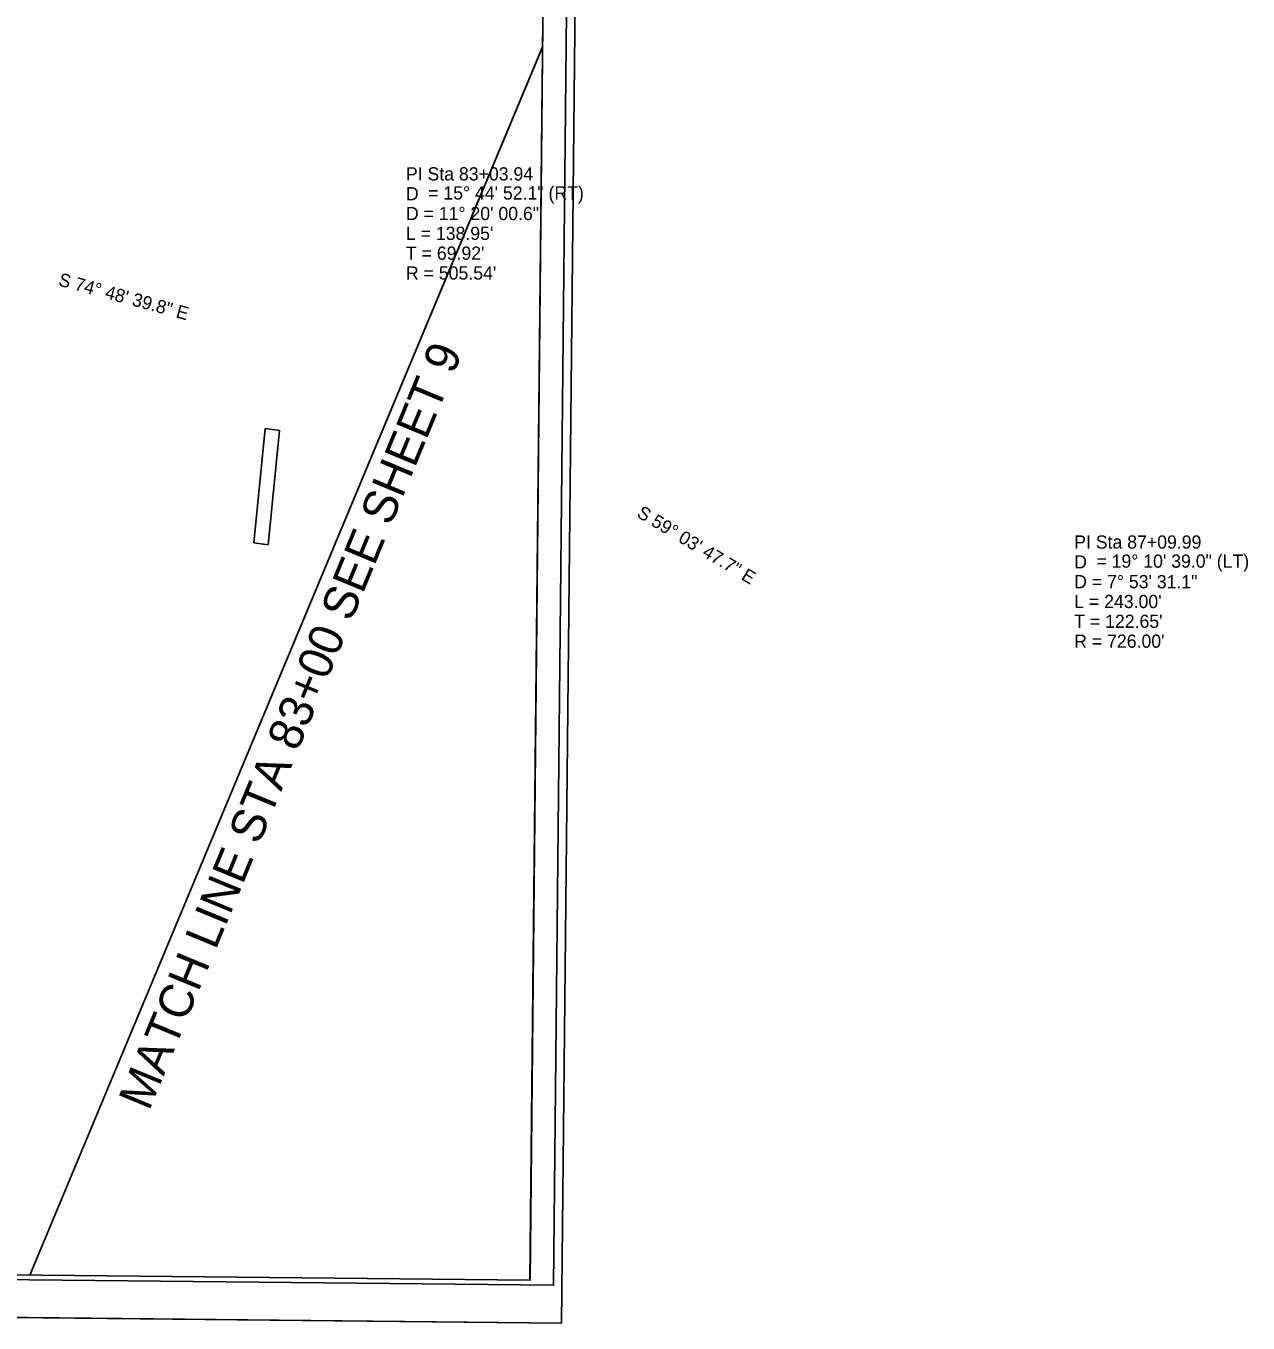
# Model space of a CAD drawing. Extents: x 928111 to 937215, y 684176 to 686530.
# Drawn here: x 934365 to 935012, y 684176 to 684863 of the extents above; entities that cross this region are included whole.
import ezdxf

# ---------------------------------------------------------------- set-up
doc = ezdxf.new("R2010")
doc.units = 0
for name, color, linetype in [('Exist Horizontal Alignment Curve and Spiral Data', 7, 'Continuous'), ('Exist Horizontal Alignment Direction Label', 7, 'Continuous'), ('Matchline', 7, 'Continuous'), ('Matchline Text', 7, 'Continuous'), ('Prop DSN Text', 7, 'Continuous'), ('Sheet Cutting Line CELL', 7, 'Continuous'), ('Sheet Layout Plan Border', 7, 'Continuous'), ('Sheet Plan CELL', 7, 'Continuous'), ('Sheet Plan Layout CELL', 7, 'Continuous'), ('Sheet Plot Border Inside CELL', 7, 'Continuous'), ('Sheet Plot Border Outside CELL', 7, 'Continuous')]:
    doc.layers.add(name, color=color, linetype=linetype)

msp = doc.modelspace()

# ---------------------------------------------------------------- linework, layer by layer
at = {"layer": 'Matchline'}
msp.add_line((934638.43, 684851.73), (934366.75, 684201.2), dxfattribs=at)
at = {"layer": 'Prop DSN Text'}
for p, q in [((934491.39, 684649.65), (934485.41, 684589.04)), ((934491.39, 684649.65), (934499.01, 684648.6)), ((934499.01, 684648.6), (934493.04, 684587.99)), ((934485.41, 684589.04), (934493.04, 684587.99))]:
    msp.add_line(p, q, dxfattribs=at)
at = {"layer": 'Sheet Cutting Line CELL'}
msp.add_line((932965.09, 684193.02), (934648.5, 684175.8), dxfattribs=at)
at = {"layer": 'Sheet Layout Plan Border'}
msp.add_line((934366.75, 684201.2), (934638.41, 684851.69), dxfattribs=at)
at = {"layer": 'Sheet Plan CELL'}
msp.add_lwpolyline([(934642.5, 685248.43), (933142.54, 685263.77), (933131.8, 684213.83), (934631.73, 684198.49)], close=True, dxfattribs=at)
at = {"layer": 'Sheet Plan Layout CELL'}
msp.add_lwpolyline([(933142.51, 685263.75), (933131.8, 684213.83), (934631.72, 684198.49), (934640.3, 685036.96), (934401.06, 685039.4), (934403.22, 685250.88)], close=True, dxfattribs=at)
at = {"layer": 'Sheet Plot Border Inside CELL'}
msp.add_lwpolyline([(932978.29, 684212.89), (934644.19, 684195.86), (934654.99, 685250.79), (932989.08, 685267.83)], close=True, dxfattribs=at)
at = {"layer": 'Sheet Plot Border Outside CELL'}
msp.add_lwpolyline([(932965.09, 684193.02), (934648.5, 684175.8), (934659.7, 685270.75), (932976.29, 685287.96)], close=True, dxfattribs=at)

# ---------------------------------------------------------------- texts
at = {"layer": 'Exist Horizontal Alignment Curve and Spiral Data'}
for s, p in [('PI Sta 83+03.94', (934566, 684781)), ('D', (934566, 684770.5)), ('= 15%%d 44\' 52.1" (RT)', (934577.77, 684770.89)), ('D = 11%%d 20\' 00.6"', (934566, 684760)), ("L = 138.95'", (934566, 684749.5)), ("T = 69.92'", (934566, 684739)), ("R = 505.54'", (934566, 684728.5)), ('PI Sta 87+09.99', (934920, 684586)), ('D', (934920, 684575.5)), ('= 19%%d 10\' 39.0" (LT)', (934931.77, 684575.89)), ('D = 7%%d 53\' 31.1"', (934920, 684565)), ("L = 243.00'", (934920, 684554.5)), ("T = 122.65'", (934920, 684544)), ("R = 726.00'", (934920, 684533.5))]:
    msp.add_text(s, height=7, dxfattribs=at).set_placement(p)
at = {"layer": 'Exist Horizontal Alignment Direction Label'}
for s, rotation, p in [('S 74%%d 48\' 39.8" E', 344.81107, (934381.45, 684725.47)), ('S 59%%d 03\' 47.7" E', 329.06326, (934687.79, 684603.14))]:
    msp.add_text(s, height=7, rotation=rotation, dxfattribs=at).set_placement(p)
at = {"layer": 'Matchline Text'}
msp.add_text('MATCH LINE STA 83+00 SEE SHEET 9', height=18, rotation=67.5533, dxfattribs=at).set_placement((934429.93, 684287.72))

doc.saveas('drawing.dxf')
